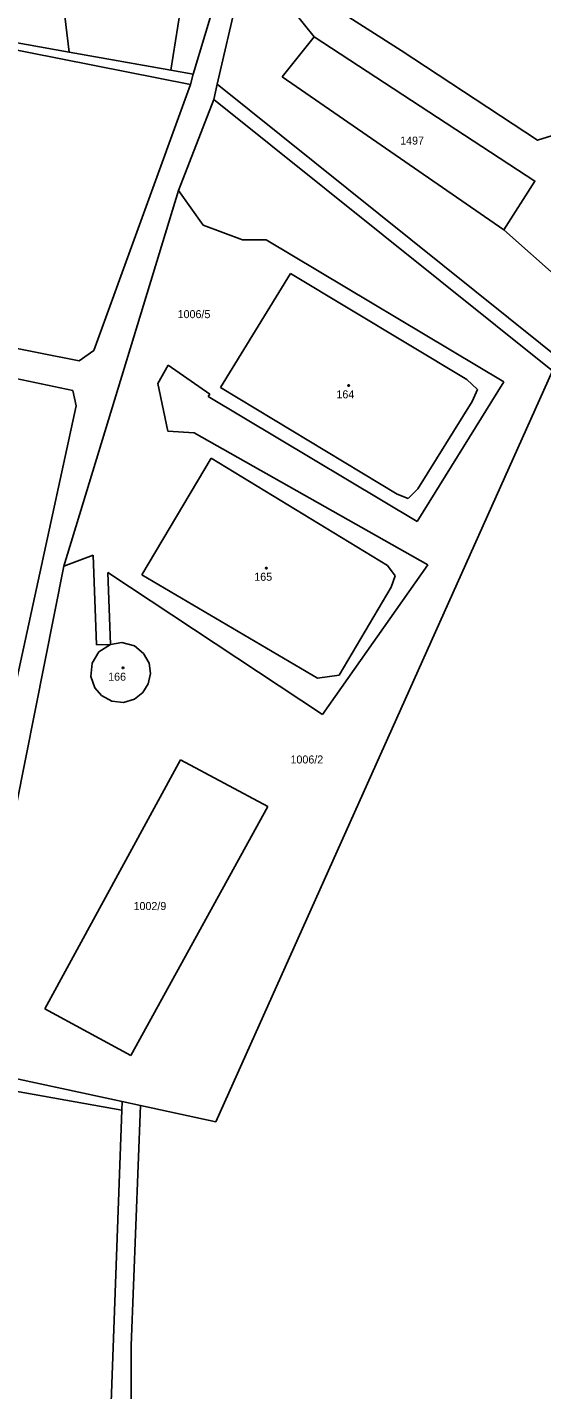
# Model space of a CAD drawing. Extents: x -850689 to -847910, y -1058374 to -1054747.
# Drawn here: x -849406.4 to -849297.1, y -1056733.6 to -1056444.2 of the extents above; entities that cross this region are included whole.
import ezdxf

# ---------------------------------------------------------------- set-up
doc = ezdxf.new("R2010")
doc.units = 0
for name, color, linetype in [('KN_BREMENA', 7, 'Continuous'), ('KN_HRANICE', 7, 'Continuous'), ('KN_KULTURY', 7, 'Continuous'), ('KN_PARCELY', 7, 'Continuous'), ('KN_STAVEBNI', 7, 'Continuous')]:
    doc.layers.add(name, color=color, linetype=linetype)

# ---------------------------------------------------------------- blocks, each defined once
blk = doc.blocks.new('402')
blk.add_lwpolyline([(0.09, 0.15), (0.18, 0), (0.09, -0.15), (-0.09, -0.15), (-0.18, 0), (-0.09, 0.15), (0.09, 0.15)])

msp = doc.modelspace()

# ---------------------------------------------------------------- linework, layer by layer
at = {"layer": 'KN_BREMENA'}
for points in [[(-849355.23, -1056367.43), (-849351.69, -1056370.82), (-849349.93, -1056375.07), (-849350.77, -1056418.49), (-849350.24, -1056427.3), (-849345.77, -1056436.61), (-849342.23, -1056439.43), (-849327.01, -1056449.14), (-849298.02, -1056468.19), (-849284.6, -1056463.96), (-849270.77, -1056447.7), (-849287.91, -1056435.18), (-849282.02, -1056427.2), (-849264.01, -1056440.34), (-849244.44, -1056411.59), (-849258.75, -1056401.09), (-849252.32, -1056392.28), (-849210.21, -1056427.21)], [(-849305.2, -1056487.17), (-849298.59, -1056476.85), (-849345.45, -1056446.21), (-849353.67, -1056435.91), (-849355.13, -1056429.06), (-849354.9, -1056417.2), (-849354.04, -1056379.97)], [(-849255.9, -1056479.47), (-849281.24, -1056508.47), (-849305.2, -1056487.17)]]:
    msp.add_lwpolyline(points, dxfattribs=at)
at = {"layer": 'KN_HRANICE'}
for p, q in [((-849401.89, -1056413.93), (-849397.43, -1056449.45)), ((-849375.87, -1056453.3), (-849372.33, -1056430.72)), ((-849364.14, -1056430.75), (-849371.16, -1056454.14)), ((-849360.36, -1056431.7), (-849366.02, -1056456.29)), ((-849371.72, -1056456.31), (-849483.86, -1056434.18)), ((-849419.09, -1056445.59), (-849397.43, -1056449.45)), ((-849352.25, -1056454.73), (-849345.45, -1056446.21)), ((-849345.45, -1056446.21), (-849298.59, -1056476.85)), ((-849397.43, -1056449.45), (-849375.87, -1056453.3)), ((-849375.87, -1056453.3), (-849371.16, -1056454.14)), ((-849392.25, -1056512.84), (-849371.72, -1056456.31)), ((-849371.16, -1056454.14), (-849371.72, -1056456.31)), ((-849366.02, -1056456.29), (-849366.76, -1056459.53)), ((-849289.39, -1056517.79), (-849366.02, -1056456.29)), ((-849305.2, -1056487.17), (-849352.25, -1056454.73)), ((-849374.29, -1056478.85), (-849366.76, -1056459.53)), ((-849366.76, -1056459.53), (-849294.89, -1056517.18)), ((-849298.59, -1056476.85), (-849305.2, -1056487.17)), ((-849398.6, -1056558.62), (-849374.29, -1056478.85)), ((-849374.29, -1056478.85), (-849369.04, -1056486.2)), ((-849369.04, -1056486.2), (-849360.68, -1056489.31)), ((-849360.68, -1056489.31), (-849355.61, -1056489.31)), ((-849355.61, -1056489.31), (-849305.18, -1056519.49)), ((-849350.46, -1056496.46), (-849365.37, -1056520.72)), ((-849313.05, -1056518.99), (-849350.46, -1056496.46)), ((-849468.95, -1056500.27), (-849395.37, -1056515.06)), ((-849468.29, -1056506.44), (-849396.69, -1056521.32)), ((-849395.37, -1056515.06), (-849392.25, -1056512.84)), ((-849376.45, -1056515.96), (-849378.64, -1056519.87)), ((-849367.58, -1056522.09), (-849376.45, -1056515.96)), ((-849294.89, -1056517.18), (-849366.33, -1056676.64)), ((-849378.64, -1056519.87), (-849376.54, -1056529.98)), ((-849305.18, -1056519.49), (-849323.59, -1056549.16)), ((-849310.8, -1056521.11), (-849313.05, -1056518.99)), ((-849396.69, -1056521.32), (-849395.95, -1056524.56)), ((-849367.95, -1056522.58), (-849367.58, -1056522.09)), ((-849323.59, -1056549.16), (-849367.95, -1056522.58)), ((-849365.37, -1056520.72), (-849327.83, -1056543.32)), ((-849311.89, -1056523.66), (-849310.8, -1056521.11)), ((-849395.95, -1056524.56), (-849420.9, -1056639.14)), ((-849323.45, -1056542.2), (-849311.89, -1056523.66)), ((-849376.54, -1056529.98), (-849370.95, -1056530.31)), ((-849370.95, -1056530.31), (-849321.34, -1056558.37)), ((-849382.03, -1056560.46), (-849367.31, -1056535.71)), ((-849367.31, -1056535.71), (-849329.91, -1056558.5)), ((-849327.83, -1056543.32), (-849325.52, -1056544.25)), ((-849325.52, -1056544.25), (-849323.45, -1056542.2)), ((-849392.34, -1056556.32), (-849398.6, -1056558.62)), ((-849392.34, -1056556.32), (-849391.63, -1056575.35)), ((-849414.91, -1056640.62), (-849398.6, -1056558.62)), ((-849343.7, -1056590.17), (-849389.23, -1056559.95)), ((-849389.23, -1056559.95), (-849388.71, -1056575.25)), ((-849344.74, -1056582.45), (-849382.03, -1056560.46)), ((-849321.34, -1056558.37), (-849343.7, -1056590.17)), ((-849329.91, -1056558.5), (-849328.28, -1056560.68)), ((-849328.28, -1056560.68), (-849329.1, -1056563.12)), ((-849329.1, -1056563.12), (-849340.13, -1056581.78)), ((-849388.71, -1056575.25), (-849386.26, -1056574.88)), ((-849386.26, -1056574.88), (-849383.61, -1056575.59)), ((-849392.59, -1056579.22), (-849391.16, -1056576.85)), ((-849391.63, -1056575.35), (-849388.71, -1056575.25)), ((-849391.16, -1056576.85), (-849388.71, -1056575.25)), ((-849383.61, -1056575.59), (-849381.66, -1056577.17)), ((-849381.66, -1056577.17), (-849380.5, -1056579.27)), ((-849392.85, -1056582.1), (-849392.59, -1056579.22)), ((-849380.19, -1056581.45), (-849380.5, -1056579.27)), ((-849392.03, -1056584.47), (-849392.85, -1056582.1)), ((-849381.83, -1056585.5), (-849380.66, -1056583.65)), ((-849380.66, -1056583.65), (-849380.19, -1056581.45)), ((-849340.13, -1056581.78), (-849344.74, -1056582.45)), ((-849392.03, -1056584.47), (-849390.61, -1056586.14)), ((-849390.61, -1056586.14), (-849388.43, -1056587.31)), ((-849383.61, -1056586.88), (-849381.83, -1056585.5)), ((-849388.43, -1056587.31), (-849385.96, -1056587.57)), ((-849385.96, -1056587.57), (-849383.61, -1056586.88)), ((-849373.81, -1056599.77), (-849402.6, -1056652.68)), ((-849355.26, -1056609.68), (-849373.81, -1056599.77)), ((-849384.36, -1056662.54), (-849355.26, -1056609.68)), ((-849402.6, -1056652.68), (-849384.36, -1056662.54)), ((-849495.08, -1056654.69), (-849386.31, -1056674.19)), ((-849413.8, -1056666.37), (-849386.24, -1056672.33)), ((-849386.31, -1056674.19), (-849386.24, -1056672.33)), ((-849386.24, -1056672.33), (-849382.3, -1056673.18)), ((-849382.3, -1056673.18), (-849384.29, -1056724.14)), ((-849382.3, -1056673.18), (-849366.33, -1056676.64)), ((-849389.98, -1056776.11), (-849386.31, -1056674.19)), ((-849384.29, -1056724.14), (-849384.29, -1056820.56))]:
    msp.add_line(p, q, dxfattribs=at)
at = {"layer": 'KN_STAVEBNI'}
for p, q in [((-849350.46, -1056496.46), (-849365.37, -1056520.72)), ((-849313.05, -1056518.99), (-849350.46, -1056496.46)), ((-849310.8, -1056521.11), (-849313.05, -1056518.99)), ((-849365.37, -1056520.72), (-849327.83, -1056543.32)), ((-849311.89, -1056523.66), (-849310.8, -1056521.11)), ((-849323.45, -1056542.2), (-849311.89, -1056523.66)), ((-849382.03, -1056560.46), (-849367.31, -1056535.71)), ((-849367.31, -1056535.71), (-849329.91, -1056558.5)), ((-849327.83, -1056543.32), (-849325.52, -1056544.25)), ((-849325.52, -1056544.25), (-849323.45, -1056542.2)), ((-849344.74, -1056582.45), (-849382.03, -1056560.46)), ((-849329.91, -1056558.5), (-849328.28, -1056560.68)), ((-849328.28, -1056560.68), (-849329.1, -1056563.12)), ((-849329.1, -1056563.12), (-849340.13, -1056581.78)), ((-849388.71, -1056575.25), (-849386.26, -1056574.88)), ((-849386.26, -1056574.88), (-849383.61, -1056575.59)), ((-849392.59, -1056579.22), (-849391.16, -1056576.85)), ((-849391.16, -1056576.85), (-849388.71, -1056575.25)), ((-849383.61, -1056575.59), (-849381.66, -1056577.17)), ((-849381.66, -1056577.17), (-849380.5, -1056579.27)), ((-849392.85, -1056582.1), (-849392.59, -1056579.22)), ((-849380.19, -1056581.45), (-849380.5, -1056579.27)), ((-849392.03, -1056584.47), (-849392.85, -1056582.1)), ((-849381.83, -1056585.5), (-849380.66, -1056583.65)), ((-849380.66, -1056583.65), (-849380.19, -1056581.45)), ((-849340.13, -1056581.78), (-849344.74, -1056582.45)), ((-849392.03, -1056584.47), (-849390.61, -1056586.14)), ((-849390.61, -1056586.14), (-849388.43, -1056587.31)), ((-849383.61, -1056586.88), (-849381.83, -1056585.5)), ((-849388.43, -1056587.31), (-849385.96, -1056587.57)), ((-849385.96, -1056587.57), (-849383.61, -1056586.88))]:
    msp.add_line(p, q, dxfattribs=at)

# ---------------------------------------------------------------- block references
at = {"layer": 'KN_KULTURY'}
for p in [(-849338.14, -1056520.29), (-849355.62, -1056559.04), (-849386.03, -1056580.22)]:
    msp.add_blockref('402', p, dxfattribs=at)

# ---------------------------------------------------------------- texts
at = {"layer": 'KN_PARCELY'}
for s, p in [('1497', (-849327.2, -1056469.1)), ('1006/5', (-849374.44, -1056505.96)), ('164', (-849340.73, -1056522.99)), ('165', (-849358.17, -1056561.74)), ('166', (-849389.19, -1056582.97)), ('1006/2', (-849350.48, -1056600.55)), ('1002/9', (-849383.8, -1056631.68))]:
    msp.add_text(s, height=1.7, dxfattribs=at).set_placement(p)

doc.saveas('drawing.dxf')
